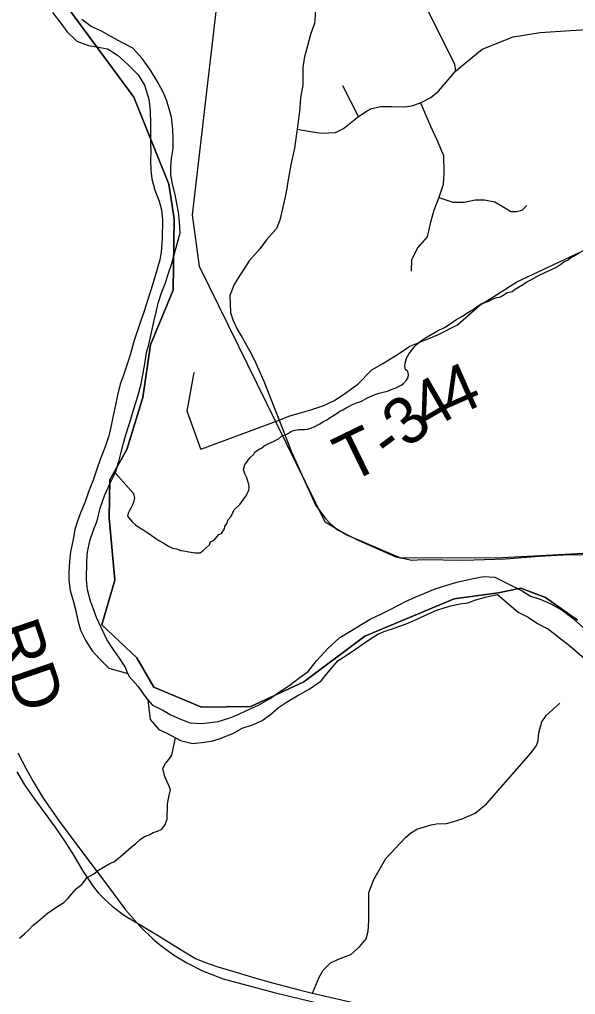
# Model space of a CAD drawing. Extents: x 44.2 to 78.2, y 4.5 to 26.5.
# Drawn here: x 51.074 to 51.74, y 19.388 to 20.558 of the extents above; entities that cross this region are included whole.
import ezdxf

# ---------------------------------------------------------------- set-up
doc = ezdxf.new("R2010")
doc.units = 0
for name, color, linetype in [('GM_X_County_Road', 7, 'Continuous'), ('GM_X_County_Road_Text', 7, 'Continuous'), ('GM_X_Major_River', 7, 'Continuous'), ('GM_X_Minor_River', 7, 'Continuous'), ('GM_X_Rail_Line', 7, 'Continuous'), ('GM_X_Township_Road', 7, 'Continuous'), ('GM_X_Township_Road_Text', 7, 'Continuous'), ('GM_X_US_Route', 7, 'Continuous')]:
    doc.layers.add(name, color=color, linetype=linetype)

msp = doc.modelspace()

# ---------------------------------------------------------------- linework, layer by layer
at = {"layer": 'GM_X_County_Road'}
msp.add_lwpolyline([(51.0704, 19.6547), (51.0797, 19.6392), (51.0909, 19.6232), (51.104, 19.6052), (51.1161, 19.5887), (51.1281, 19.5713), (51.1391, 19.5537), (51.1494, 19.5362), (51.1611, 19.5184), (51.1678, 19.5095), (51.175, 19.5022), (51.1847, 19.4935), (51.1997, 19.4824), (51.2233, 19.4684), (51.2413, 19.4575), (51.2676, 19.441), (51.2849, 19.4308), (51.2954, 19.4262), (51.3115, 19.4208), (51.3211, 19.4178), (51.3386, 19.4126), (51.3544, 19.4079), (51.377, 19.4015), (51.4076, 19.3937), (51.4252, 19.3893), (51.6126, 19.3459)], dxfattribs=at)
at = {"layer": 'GM_X_Major_River'}
for points in [[(51.1131, 20.5661), (51.1231, 20.5533), (51.1305, 20.5433), (51.1424, 20.5316), (51.1563, 20.5264), (51.1661, 20.5247), (51.179, 20.5225), (51.1906, 20.515), (51.2036, 20.5037), (51.2159, 20.4913), (51.2236, 20.4786), (51.2289, 20.4621), (51.2305, 20.4484), (51.2309, 20.4317)], [(51.1545, 19.9076), (51.1551, 19.9182), (51.1581, 19.9319), (51.1629, 19.9458), (51.1666, 19.956), (51.1703, 19.9712), (51.176, 19.987), (51.1824, 20.001), (51.1887, 20.0141), (51.1928, 20.027), (51.1953, 20.0368), (51.1982, 20.0493), (51.2011, 20.0591), (51.2052, 20.0716), (51.2093, 20.0848), (51.2122, 20.0954), (51.2154, 20.1056), (51.2195, 20.1204), (51.2221, 20.1333), (51.2243, 20.1469), (51.226, 20.1579), (51.2289, 20.1677), (51.2319, 20.1818), (51.2348, 20.1946), (51.2373, 20.2048), (51.2399, 20.217), (51.2444, 20.2309), (51.2488, 20.2415), (51.252, 20.2521), (51.2565, 20.2649), (51.2594, 20.2767), (51.2627, 20.2884), (51.2664, 20.3016), (51.2656, 20.3149), (51.2643, 20.3264), (51.2622, 20.3367), (51.2602, 20.3474), (51.257, 20.36), (51.255, 20.3711), (51.2552, 20.3806), (51.2558, 20.3908), (51.258, 20.4026), (51.2579, 20.4155), (51.2577, 20.4258), (51.2558, 20.4403), (51.2533, 20.4502), (51.2498, 20.4606), (51.2458, 20.4705), (51.2389, 20.4836), (51.2308, 20.4967), (51.2209, 20.5106), (51.2094, 20.523), (51.1962, 20.5301), (51.1839, 20.5368), (51.1719, 20.5436), (51.1595, 20.5491), (51.1483, 20.5577)], [(51.2309, 20.4317), (51.2306, 20.4191), (51.2308, 20.4088), (51.231, 20.3993), (51.2307, 20.3894), (51.2312, 20.3765), (51.2325, 20.3662), (51.236, 20.3528), (51.241, 20.3394), (51.2438, 20.3291), (51.2451, 20.3176), (51.2446, 20.2945), (51.2435, 20.2785), (51.2418, 20.269), (51.2385, 20.2569), (51.2344, 20.2433), (51.2311, 20.2327), (51.227, 20.2203), (51.2233, 20.2074), (51.2189, 20.1953), (51.2108, 20.1712), (51.2067, 20.1564), (51.203, 20.1451), (51.1985, 20.1307), (51.1945, 20.1201), (51.1911, 20.1069), (51.1882, 20.0933), (51.1856, 20.0804), (51.1835, 20.0705), (51.1806, 20.0581), (51.1765, 20.0448), (51.1705, 20.0294), (51.1664, 20.018), (51.162, 20.0048), (51.1563, 19.9908), (51.1523, 19.9788), (51.1467, 19.9656), (51.1434, 19.9554), (51.1402, 19.9455), (51.1376, 19.9315), (51.135, 19.9186), (51.1336, 19.9073), (51.133, 19.8947), (51.1328, 19.8848), (51.1344, 19.8722), (51.1383, 19.8589), (51.1411, 19.8478), (51.1438, 19.8363), (51.147, 19.8248), (51.1532, 19.8121), (51.1609, 19.7998), (51.1698, 19.7901), (51.1809, 19.7792), (51.2035, 19.7729)], [(51.2035, 19.7729), (51.2003, 19.7807), (51.1937, 19.7911), (51.1852, 19.8031), (51.1783, 19.8135), (51.1721, 19.8273), (51.1659, 19.84), (51.1624, 19.85), (51.1588, 19.8596), (51.1553, 19.873), (51.154, 19.8852), (51.1545, 19.9076)], [(51.2277, 19.7412), (51.2331, 19.7348), (51.2455, 19.7288), (51.2552, 19.7233), (51.2669, 19.7178), (51.2782, 19.7137), (51.2918, 19.7127), (51.3021, 19.714), (51.312, 19.7153), (51.3258, 19.7196), (51.3357, 19.7236), (51.3457, 19.7283), (51.3603, 19.7348), (51.3741, 19.7429), (51.3868, 19.7514), (51.3965, 19.7581), (51.4104, 19.7684), (51.42, 19.7751), (51.4298, 19.7878), (51.4434, 19.8027), (51.4577, 19.8161), (51.4719, 19.8242), (51.4843, 19.8319), (51.4943, 19.8378), (51.5085, 19.8448), (51.5215, 19.851), (51.5365, 19.859), (51.5488, 19.8649), (51.5599, 19.8692), (51.5721, 19.8743), (51.5863, 19.8789), (51.5981, 19.8825), (51.6179, 19.8866), (51.6305, 19.889), (51.6438, 19.8884)], [(51.6438, 19.8884), (51.6763, 19.8721), (51.6865, 19.8656), (51.6982, 19.862), (51.711, 19.8565), (51.7245, 19.8487), (51.7361, 19.8401), (51.7495, 19.8281)], [(51.2277, 19.7412), (51.2305, 19.7177), (51.2408, 19.7054), (51.251, 19.7006), (51.2667, 19.6923), (51.2811, 19.6889), (51.2955, 19.6902), (51.3054, 19.6919), (51.3157, 19.6951), (51.3303, 19.7012), (51.3407, 19.7071), (51.3541, 19.7114), (51.3648, 19.7165), (51.3745, 19.7235), (51.3841, 19.7321), (51.3938, 19.7383), (51.4068, 19.7461), (51.421, 19.7538), (51.4353, 19.7641), (51.4439, 19.7742), (51.4556, 19.788), (51.4691, 19.7969), (51.4933, 19.8135), (51.5034, 19.8198), (51.5129, 19.8238), (51.5229, 19.8273), (51.5374, 19.8324), (51.5478, 19.8367), (51.5604, 19.8429), (51.5742, 19.8487), (51.5895, 19.8537), (51.6017, 19.8562), (51.6112, 19.8575), (51.6208, 19.8611), (51.6338, 19.8646), (51.6471, 19.8674)], [(51.6471, 19.8674), (51.6715, 19.8465), (51.6837, 19.8402), (51.695, 19.8327), (51.7082, 19.8261), (51.7213, 19.8156), (51.7336, 19.8059), (51.7451, 19.7958), (51.7582, 19.7846), (51.7713, 19.7745), (51.781, 19.766), (51.7907, 19.7582), (51.803, 19.7485), (51.8131, 19.7404), (51.8257, 19.7276), (51.8384, 19.7153), (51.8518, 19.7044), (51.8654, 19.6996), (51.8779, 19.6991), (51.8907, 19.6992), (51.9029, 19.6998)], [(51.2035, 19.7729), (51.205, 19.7692), (51.2154, 19.7576), (51.2242, 19.7453), (51.2277, 19.7412)]]:
    msp.add_lwpolyline(points, dxfattribs=at)
at = {"layer": 'GM_X_Minor_River'}
for points in [[(51.534, 20.1207), (51.5379, 20.1248), (51.5399, 20.1281), (51.5403, 20.1315), (51.5393, 20.135), (51.5367, 20.1377), (51.5356, 20.1412), (51.5361, 20.1453), (51.5378, 20.151), (51.541, 20.1569), (51.5449, 20.1618), (51.5492, 20.167), (51.5543, 20.171), (51.5597, 20.1751), (51.5751, 20.1838), (51.5832, 20.1881), (51.5901, 20.1925), (51.5971, 20.1972), (51.604, 20.2012), (51.6075, 20.203), (51.6102, 20.2052), (51.6141, 20.2074), (51.6168, 20.2092), (51.6195, 20.2107), (51.6264, 20.2158), (51.6295, 20.2172), (51.6352, 20.219), (51.6425, 20.2226), (51.646, 20.224), (51.6506, 20.2247), (51.6544, 20.2272), (51.6575, 20.2294), (51.6644, 20.2311), (51.6679, 20.2341), (51.6779, 20.2399), (51.6822, 20.2428), (51.6868, 20.2453), (51.6976, 20.2511), (51.7168, 20.2601), (51.7203, 20.2623), (51.723, 20.2641), (51.7265, 20.2667), (51.7307, 20.2688), (51.7346, 20.2714), (51.7392, 20.2739), (51.745, 20.2772)], [(51.1884, 20.0135), (51.2104, 19.9888), (51.2114, 19.9835), (51.2106, 19.9797), (51.2093, 19.9752), (51.2073, 19.971), (51.2053, 19.9677), (51.2041, 19.9651), (51.2033, 19.9617), (51.2051, 19.959), (51.2088, 19.9547), (51.2129, 19.9512), (51.2181, 19.9476), (51.2226, 19.9448), (51.2264, 19.9425), (51.2316, 19.9389), (51.2372, 19.9346), (51.2409, 19.9322), (51.2458, 19.9294), (51.2525, 19.9255), (51.257, 19.9231), (51.2623, 19.9222), (51.2668, 19.9205), (51.2702, 19.9201), (51.2729, 19.9196), (51.2766, 19.9188), (51.2846, 19.9174), (51.2869, 19.9174), (51.2903, 19.9176), (51.2945, 19.9206), (51.3016, 19.9272), (51.3028, 19.9306), (51.3074, 19.9331), (51.3109, 19.9372), (51.3129, 19.9394), (51.316, 19.9409), (51.3195, 19.9465), (51.32, 19.9495), (51.3227, 19.9532), (51.3236, 19.9566), (51.3271, 19.9607), (51.3311, 19.9693), (51.3377, 19.9756), (51.342, 19.9812), (51.3452, 19.9856), (51.3476, 19.9901), (51.3488, 19.9931), (51.3489, 19.9962), (51.3486, 19.9996), (51.3475, 20.0034), (51.3461, 20.0076), (51.3443, 20.0115), (51.3429, 20.0153), (51.3422, 20.018), (51.3439, 20.0232), (51.3498, 20.0314), (51.3545, 20.0359), (51.3557, 20.0385), (51.3611, 20.0418), (51.3638, 20.0432), (51.3672, 20.0458), (51.3742, 20.0494), (51.3776, 20.0508), (51.3811, 20.0526), (51.3842, 20.0544), (51.3877, 20.0574), (51.3934, 20.0595), (51.3965, 20.0613), (51.3988, 20.0628), (51.4023, 20.0642), (51.4061, 20.0652), (51.4088, 20.0656), (51.4114, 20.0655), (51.4156, 20.0654), (51.419, 20.066), (51.4225, 20.0671), (51.4271, 20.0689), (51.434, 20.0725), (51.4382, 20.075), (51.4421, 20.0772), (51.4464, 20.0801), (51.4514, 20.083), (51.4548, 20.0852), (51.4579, 20.0874), (51.4614, 20.0892), (51.4653, 20.0914), (51.4687, 20.0932), (51.4729, 20.0954), (51.4779, 20.0975), (51.4818, 20.0986), (51.4845, 20.1), (51.4902, 20.1033), (51.496, 20.1058), (51.5002, 20.1076), (51.5048, 20.1093), (51.5098, 20.1103), (51.5151, 20.1117), (51.5194, 20.1135), (51.524, 20.1153), (51.5313, 20.1189), (51.534, 20.1207)], [(51.0736, 19.455), (51.0798, 19.4603), (51.0848, 19.4651), (51.0902, 19.4707), (51.0956, 19.4752), (51.1014, 19.48), (51.1068, 19.4849), (51.1133, 19.4893), (51.121, 19.4945), (51.1267, 19.4978), (51.1321, 19.5031), (51.1364, 19.5083), (51.1422, 19.5147), (51.1484, 19.5195), (51.155, 19.5281), (51.1626, 19.5325), (51.1684, 19.5366), (51.1742, 19.5403), (51.1818, 19.5448), (51.1868, 19.5466), (51.1945, 19.5529), (51.2076, 19.5644), (51.2126, 19.5685), (51.2184, 19.5734), (51.2237, 19.5771), (51.2291, 19.5793), (51.2341, 19.5819), (51.239, 19.5837), (51.2444, 19.5859), (51.2479, 19.5907), (51.2507, 19.5979), (51.2508, 19.6032), (51.2513, 19.6104), (51.251, 19.6165), (51.2522, 19.6222), (51.2535, 19.6283), (51.2547, 19.6332), (51.2529, 19.6385), (51.2504, 19.6435), (51.2478, 19.6489), (51.2457, 19.6588), (51.2488, 19.6648), (51.2527, 19.6697), (51.2562, 19.6746), (51.2608, 19.6954)]]:
    msp.add_lwpolyline(points, dxfattribs=at)
at = {"layer": 'GM_X_Rail_Line'}
for points in [[(51.7576, 19.9172), (51.6529, 19.9117), (51.5311, 19.911), (51.4655, 19.9391), (51.4402, 19.9542), (51.2895, 20.2613), (51.2813, 20.3233), (51.3434, 20.8596), (51.3339, 20.9662), (51.3307, 21.0331), (51.3143, 21.0616), (51.2918, 21.0838), (51.0931, 21.2312)], [(51.1015, 20.6127), (51.2106, 20.4645), (51.2527, 20.36), (51.2592, 20.3185), (51.258, 20.2327), (51.2306, 20.167), (51.2215, 20.1041), (51.2025, 20.0414), (51.1818, 20.0052), (51.181, 19.9597), (51.188, 19.8847), (51.1722, 19.831), (51.2143, 19.7915), (51.2349, 19.7562), (51.2918, 19.7324), (51.3509, 19.7333), (51.4148, 19.7626), (51.4878, 19.8176), (51.5948, 19.8625), (51.6476, 19.8697), (51.6749, 19.8752), (51.7043, 19.8639), (51.7427, 19.8368)], [(51.7427, 19.8368), (51.7043, 19.8639), (51.6749, 19.8752), (51.6476, 19.8697), (51.5948, 19.8625), (51.4878, 19.8176), (51.4148, 19.7626), (51.3509, 19.7333), (51.2918, 19.7324), (51.2349, 19.7562), (51.2143, 19.7915), (51.1722, 19.831), (51.188, 19.8847), (51.181, 19.9597), (51.1818, 20.0052), (51.2025, 20.0414), (51.2215, 20.1041), (51.2306, 20.167), (51.258, 20.2327), (51.2592, 20.3185), (51.2527, 20.36), (51.2106, 20.4645), (51.1015, 20.6127)], [(51.0718, 19.6774), (51.0821, 19.6574), (51.09, 19.6432), (51.1021, 19.6232), (51.1205, 19.5967), (51.1437, 19.5655), (51.179, 19.5182), (51.2008, 19.4893), (51.2188, 19.4686), (51.2334, 19.4543), (51.2414, 19.4476), (51.2584, 19.435), (51.2744, 19.4255), (51.293, 19.4158), (51.3178, 19.4062), (51.3792, 19.39), (51.8335, 19.2809)]]:
    msp.add_lwpolyline(points, dxfattribs=at)
at = {"layer": 'GM_X_Township_Road'}
for p, q in [((51.4803, 20.441), (51.4616, 20.478)), ((51.291, 20.0419), (51.3852, 20.0768))]:
    msp.add_line(p, q, dxfattribs=at)
for points in [[(51.5971, 20.4958), (51.5956, 20.5035), (51.5301, 20.6354)], [(51.4067, 20.426), (51.4228, 20.423), (51.4358, 20.4211), (51.4525, 20.4219), (51.4624, 20.4269), (51.4803, 20.441), (51.4904, 20.448), (51.4958, 20.4507), (51.5071, 20.4531), (51.5196, 20.453), (51.5353, 20.4526), (51.544, 20.454), (51.5546, 20.4577), (51.567, 20.4639), (51.5762, 20.4714), (51.5971, 20.4958), (51.6286, 20.5219), (51.6655, 20.5368), (51.6982, 20.5421), (51.7345, 20.5445), (51.7684, 20.5463)], [(51.5546, 20.4577), (51.5666, 20.4297), (51.5741, 20.4131), (51.5821, 20.3942), (51.5826, 20.3737), (51.5816, 20.3594), (51.5767, 20.3441), (51.5702, 20.3275), (51.5697, 20.3256)], [(51.5767, 20.3441), (51.5933, 20.3384), (51.6068, 20.3384), (51.6203, 20.3412), (51.6312, 20.3412), (51.6436, 20.3386), (51.6543, 20.3324), (51.6628, 20.327), (51.6698, 20.3272), (51.6766, 20.3288), (51.682, 20.3342)], [(51.5697, 20.3256), (51.5666, 20.3145), (51.5624, 20.2969), (51.5515, 20.2841), (51.5437, 20.2691), (51.5435, 20.2556)], [(51.3852, 20.0768), (51.3966, 20.0815), (51.4092, 20.0852), (51.4232, 20.0891), (51.4386, 20.0943), (51.4515, 20.1002), (51.4663, 20.1105), (51.4796, 20.1201), (51.4963, 20.1372), (51.5095, 20.1449), (51.5268, 20.1557), (51.5418, 20.1655), (51.5598, 20.1727), (51.576, 20.1795), (51.5991, 20.1911), (51.6257, 20.2149), (51.6425, 20.2251), (51.6701, 20.2428), (51.7791, 20.2941), (51.7952, 20.3005), (51.8123, 20.3043), (51.8346, 20.3038), (51.8508, 20.3011)], [(51.291, 20.0419), (51.2748, 20.0875), (51.2831, 20.134)], [(51.4252, 19.3893), (51.4329, 19.4082), (51.4379, 19.4169), (51.4466, 19.4255), (51.4584, 19.4307), (51.4711, 19.4357), (51.4814, 19.4446), (51.4892, 19.4545), (51.4917, 19.4634), (51.4927, 19.476), (51.4927, 19.4947), (51.4927, 19.5098), (51.4984, 19.5257), (51.5129, 19.5509), (51.5366, 19.5761), (51.5424, 19.5811), (51.5503, 19.5858), (51.5583, 19.5885), (51.5675, 19.591), (51.5737, 19.5922), (51.5858, 19.5928), (51.5929, 19.5949), (51.6044, 19.5982), (51.6202, 19.605), (51.6339, 19.6165), (51.6873, 19.6776), (51.6937, 19.6864), (51.6957, 19.6922), (51.6966, 19.7015), (51.7002, 19.7146), (51.7053, 19.7224), (51.7218, 19.7373)]]:
    msp.add_lwpolyline(points, dxfattribs=at)
at = {"layer": 'GM_X_US_Route'}
for points in [[(51.3962, 20.6388), (51.3972, 20.6372), (51.4035, 20.6245), (51.4165, 20.6041), (51.4221, 20.5893), (51.4288, 20.5737), (51.4284, 20.5625), (51.4273, 20.5529), (51.4232, 20.5407), (51.4165, 20.517)], [(51.4165, 20.517), (51.4154, 20.5132), (51.4136, 20.4998), (51.4135, 20.4786), (51.4106, 20.4635), (51.4093, 20.4465)], [(51.4093, 20.4465), (51.4091, 20.4445), (51.4067, 20.426)], [(51.4067, 20.426), (51.4034, 20.4033), (51.3991, 20.3833), (51.3952, 20.3608), (51.3941, 20.3548)], [(51.3941, 20.3548), (51.3924, 20.3447), (51.3858, 20.3166), (51.382, 20.3069), (51.3699, 20.2931), (51.362, 20.2823), (51.3491, 20.2678), (51.3354, 20.2469), (51.3309, 20.2394), (51.326, 20.2265), (51.3263, 20.2159), (51.3267, 20.2061), (51.3294, 20.1971), (51.3348, 20.1861), (51.3405, 20.1759), (51.3499, 20.1595), (51.3554, 20.1489), (51.3667, 20.1236), (51.3739, 20.1051), (51.3852, 20.0768), (51.3998, 20.0389), (51.4164, 20.0025), (51.4292, 19.9744), (51.4406, 19.9586), (51.4462, 19.9528), (51.4549, 19.9451), (51.4799, 19.9329), (51.5092, 19.9196), (51.525, 19.9128), (51.5355, 19.9107), (51.5439, 19.9089), (51.5579, 19.9094), (51.6063, 19.9087), (51.6563, 19.9102), (51.697, 19.9137), (51.7255, 19.9152), (51.7501, 19.9154)]]:
    msp.add_lwpolyline(points, dxfattribs=at)

# ---------------------------------------------------------------- texts
at = {"layer": 'GM_X_County_Road_Text'}
msp.add_text('RD', height=0.05682, rotation=288.8938, dxfattribs=at).set_placement((51.0401, 19.8257))
at = {"layer": 'GM_X_Township_Road_Text'}
for s, rotation, p in [('4', 23.7992, (51.5925, 20.0794)), ('4', 29.965, (51.5636, 20.0626)), ('3', 39.9512, (51.5389, 20.0416)), ('T', 25.9671, (51.4693, 20.0009)), ('-', 36.7076, (51.5175, 20.0255))]:
    msp.add_text(s, height=0.0568, rotation=rotation, dxfattribs=at).set_placement(p)

doc.saveas('drawing.dxf')
